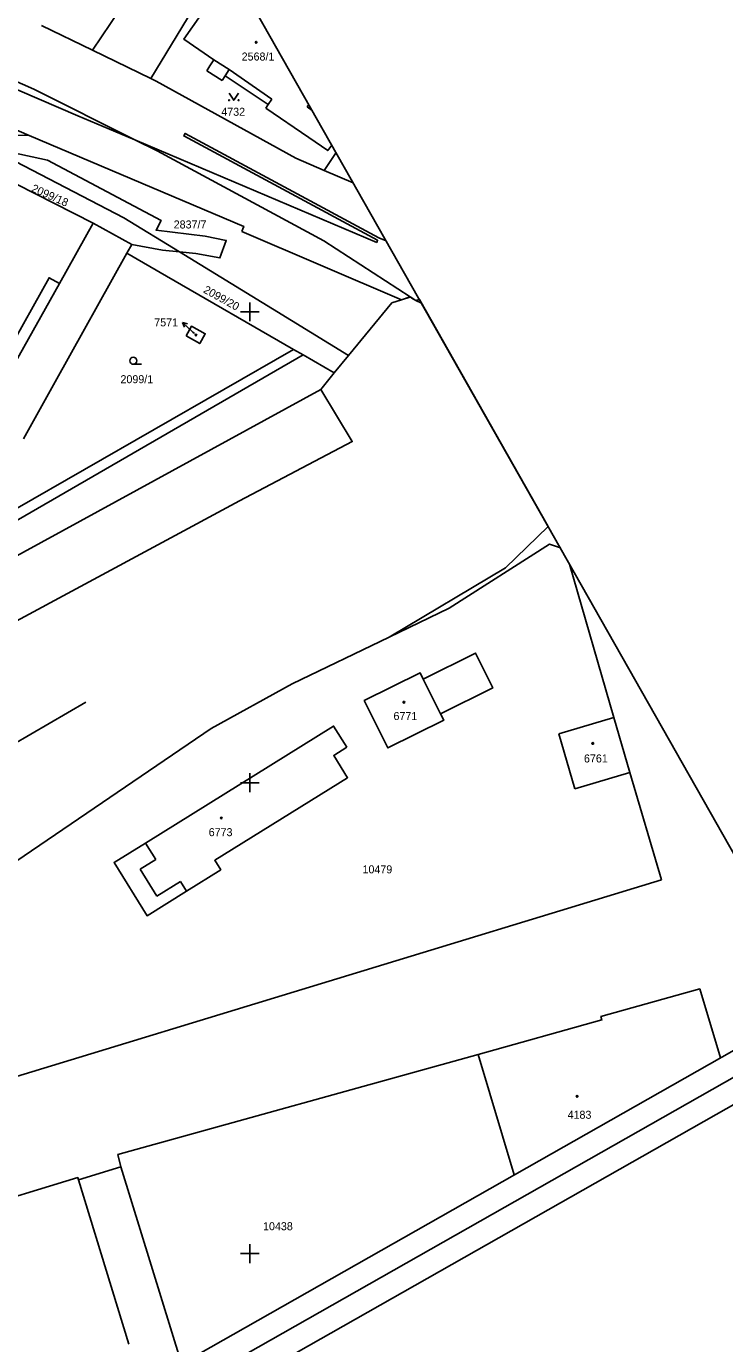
# Model space of a CAD drawing. Extents: x -566165 to -565287, y -1203064 to -1202391.
# Drawn here: x -565647.5 to -565499.2, y -1202819.1 to -1202539.4 of the extents above; entities that cross this region are included whole.
import ezdxf

# ---------------------------------------------------------------- set-up
doc = ezdxf.new("R2010")
doc.units = 0
for name, color, linetype in [('CD', 7, 'Continuous'), ('Hranice parcel', 7, 'Continuous'), ('Parcelní čísla', 7, 'Continuous'), ('Pop  PČ popisy', 7, 'Continuous'), ('Vnitřní kresba', 7, 'Continuous'), ('Vrstva 1', 7, 'Continuous'), ('Vrstva 5', 7, 'Continuous'), ('Značky budov', 7, 'Continuous'), ('Značky kultur', 7, 'Continuous'), ('ČD pro SŽDC', 7, 'Continuous')]:
    doc.layers.add(name, color=color, linetype=linetype)

msp = doc.modelspace()

# ---------------------------------------------------------------- linework, layer by layer
at = {"layer": 'CD'}
for points in [[(-565834.73, -1202732.72), (-565824.28, -1202726.13), (-565816.76, -1202721.27), (-565816.24, -1202720.98), (-565795.32, -1202709.38), (-565783.5, -1202707.11), (-565769.79, -1202704.47), (-565716.98, -1202692.29), (-565668.65, -1202665.75), (-565651.82, -1202653.08), (-565584.94, -1202616.47), (-565582.08, -1202612.99), (-565579.05, -1202609.31), (-565569.85, -1202598.11), (-565567.82, -1202597.46), (-565565.95, -1202596.85), (-565564.75, -1202597.63), (-565564, -1202597.36)], [(-565651.82, -1202653.08), (-565584.94, -1202616.47), (-565582.08, -1202612.99), (-565579.05, -1202609.31), (-565569.85, -1202598.11), (-565567.82, -1202597.46), (-565565.95, -1202596.85), (-565564.75, -1202597.63), (-565564, -1202597.36)], [(-565564, -1202597.36), (-565536.63, -1202645.61)], [(-565564, -1202597.36), (-565536.63, -1202645.61)], [(-565536.63, -1202645.61), (-565545.69, -1202654.38), (-565570.41, -1202669.07), (-565591.05, -1202679), (-565608.23, -1202688.5), (-565651.3, -1202717.76), (-565670.03, -1202715.16), (-565703.34, -1202733.61), (-565726.67, -1202746.32), (-565751.56, -1202766.01), (-565767.54, -1202780.11)], [(-565536.63, -1202645.61), (-565545.69, -1202654.38), (-565570.41, -1202669.07), (-565591.05, -1202679), (-565608.23, -1202688.5), (-565651.3, -1202717.76)]]:
    msp.add_lwpolyline(points, dxfattribs=at)
at = {"layer": 'Hranice parcel'}
for p, q in [((-565619.01, -1202523.03), (-565633.46, -1202544.45)), ((-565675.68, -1202539.58), (-565645.92, -1202552.72)), ((-565633.46, -1202544.45), (-565644.29, -1202539.18)), ((-565621.07, -1202550.47), (-565633.46, -1202544.45)), ((-565619.9, -1202551.04), (-565621.07, -1202550.47)), ((-565590.24, -1202567.4), (-565619.9, -1202551.04)), ((-565609.16, -1202548.83), (-565605.89, -1202550.88)), ((-565645.92, -1202552.72), (-565624.41, -1202563.49)), ((-565646.9, -1202562.53), (-565666.21, -1202554.22)), ((-565636.53, -1202558.35), (-565624.41, -1202563.49)), ((-565624.41, -1202563.49), (-565573.07, -1202585.25)), ((-565619.71, -1202565.84), (-565624.41, -1202563.49)), ((-565661.08, -1202567.11), (-565633.3, -1202581.16)), ((-565626.76, -1202580.01), (-565653.37, -1202566.21)), ((-565584.23, -1202569.97), (-565590.24, -1202567.4)), ((-565581.69, -1202566.18), (-565584.23, -1202569.97)), ((-565578.03, -1202572.63), (-565584.23, -1202569.97)), ((-565625.1, -1202585.67), (-565633.3, -1202581.16)), ((-565614.95, -1202587.27), (-565626.76, -1202580.01)), ((-565601.74, -1202582.95), (-565567.82, -1202597.46)), ((-565641.33, -1202614.86), (-565626.14, -1202587.55)), ((-565626.14, -1202587.55), (-565625.1, -1202585.67)), ((-565617.71, -1202592.41), (-565626.14, -1202587.55)), ((-565625.1, -1202585.67), (-565618.55, -1202586.91)), ((-565618.55, -1202586.91), (-565614.95, -1202587.27)), ((-565614.95, -1202587.27), (-565611.48, -1202587.61)), ((-565590.75, -1202607.97), (-565617.71, -1202592.41)), ((-565721.08, -1202685.53), (-565588.7, -1202609.16)), ((-565649.94, -1202642), (-565590.75, -1202607.97)), ((-565588.7, -1202609.16), (-565590.75, -1202607.97)), ((-565582.08, -1202612.99), (-565588.7, -1202609.16)), ((-565582.08, -1202612.99), (-565579.05, -1202609.31)), ((-565648.07, -1202626.98), (-565641.33, -1202614.86)), ((-565584.94, -1202616.47), (-565582.08, -1202612.99)), ((-565532.12, -1202653.56), (-565522.73, -1202686.16)), ((-565522.73, -1202686.16), (-565534.4, -1202689.63)), ((-565519.28, -1202697.85), (-565522.73, -1202686.16)), ((-565534.4, -1202689.63), (-565530.97, -1202701.28)), ((-565530.97, -1202701.28), (-565519.28, -1202697.85)), ((-565519.28, -1202697.85), (-565512.6, -1202720.6)), ((-565512.6, -1202720.6), (-565676.1, -1202770.5)), ((-565627.41, -1202781.58), (-565636.4, -1202784.32)), ((-565636.4, -1202784.32), (-565625.72, -1202819.22))]:
    msp.add_line(p, q, dxfattribs=at)
for points in [[(-565621.07, -1202550.47), (-565608.88, -1202530.33), (-565619.01, -1202523.03)], [(-565605.32, -1202529.54), (-565608.96, -1202534.8), (-565608.59, -1202535.06), (-565610, -1202537.1), (-565610.37, -1202536.85), (-565614.02, -1202542.13), (-565607.67, -1202546.46), (-565608.49, -1202547.77), (-565609.16, -1202548.83)], [(-565677.65, -1202540.7), (-565636.53, -1202558.35)], [(-565605.89, -1202550.88), (-565605.27, -1202549.9), (-565596.09, -1202555.97), (-565596.62, -1202556.75)], [(-565596.62, -1202556.75), (-565587.5, -1202563), (-565583.45, -1202565.75), (-565582.6, -1202564.58)], [(-565573.07, -1202585.25), (-565572.88, -1202584.8), (-565614.04, -1202562.63), (-565613.75, -1202562.1), (-565572.62, -1202584.26), (-565571.05, -1202584.93)], [(-565611.48, -1202587.61), (-565606.37, -1202588.55), (-565605.02, -1202584.84), (-565609.5, -1202583.94), (-565619.91, -1202582.67), (-565618.87, -1202580.59), (-565643.02, -1202567.83), (-565650.49, -1202566.2), (-565652.02, -1202564.43), (-565650.55, -1202562.52), (-565646.9, -1202562.53)], [(-565646.9, -1202562.53), (-565601.29, -1202581.88), (-565601.51, -1202582.4), (-565601.74, -1202582.95)], [(-565565.95, -1202596.85), (-565584.32, -1202584.93), (-565619.71, -1202565.84)], [(-565633.3, -1202581.16), (-565640.46, -1202593.97), (-565642.65, -1202592.75), (-565651.52, -1202608.61), (-565660.47, -1202604.69)], [(-565579.05, -1202609.31), (-565595.21, -1202599.39), (-565614.95, -1202587.27)], [(-565579.05, -1202609.31), (-565569.85, -1202598.11), (-565567.82, -1202597.46)], [(-565567.82, -1202597.46), (-565566.05, -1202596.88), (-565565.95, -1202596.85)], [(-565565.95, -1202596.85), (-565565.61, -1202597.07), (-565564.75, -1202597.63), (-565564.51, -1202597.54), (-565564, -1202597.36)], [(-565613.57, -1202605.13), (-565612.41, -1202603.05), (-565609.49, -1202604.67), (-565610.64, -1202606.75), (-565613.57, -1202605.13)], [(-565716.98, -1202692.29), (-565668.65, -1202665.75), (-565651.82, -1202653.08), (-565584.94, -1202616.47)], [(-565536.63, -1202645.61), (-565545.69, -1202654.38), (-565570.41, -1202669.07)], [(-565570.41, -1202669.07), (-565557.7, -1202662.95), (-565536.35, -1202649.35), (-565534.06, -1202650.14)], [(-565651.3, -1202717.76), (-565608.23, -1202688.5), (-565591.05, -1202679), (-565570.41, -1202669.07)], [(-565559.51, -1202685.39), (-565548.4, -1202679.87), (-565552.07, -1202672.48), (-565563.18, -1202678), (-565563.85, -1202676.66), (-565575.71, -1202682.55), (-565570.71, -1202692.62), (-565558.84, -1202686.73), (-565559.51, -1202685.39)], [(-565579.42, -1202692.47), (-565582.22, -1202687.97), (-565622.19, -1202712.8), (-565628.85, -1202716.94), (-565621.84, -1202728.24), (-565613.44, -1202723.01), (-565606.19, -1202718.49), (-565607.46, -1202716.45), (-565579.26, -1202698.93), (-565582.2, -1202694.2), (-565579.42, -1202692.47)], [(-565500.07, -1202758.42), (-565504.46, -1202743.77), (-565525.45, -1202749.61), (-565525.24, -1202750.38), (-565551.54, -1202757.69)], [(-565627.41, -1202781.58), (-565628.05, -1202778.97), (-565551.54, -1202757.69)], [(-565551.54, -1202757.69), (-565543.85, -1202783.26)], [(-565614.54, -1202823.36), (-565627.41, -1202781.58)], [(-565723.1, -1202832.75), (-565729.26, -1202812.13), (-565636.55, -1202783.84), (-565636.4, -1202784.32)]]:
    msp.add_lwpolyline(points, dxfattribs=at)
at = {"layer": 'Pop  PČ popisy'}
for p, q in [((-565612.12, -1202604.29), (-565614.32, -1202602.24)), ((-565614.32, -1202602.24), (-565613.24, -1202602.56)), ((-565614.32, -1202602.24), (-565613.92, -1202603.29)), ((-565611.78, -1202604.61), (-565612.12, -1202604.29))]:
    msp.add_line(p, q, dxfattribs=at)
at = {"layer": 'Vnitřní kresba'}
for p, q in [((-565604.4, -1202548.51), (-565607.67, -1202546.46)), ((-565604.4, -1202548.51), (-565605.27, -1202549.9)), ((-565595.31, -1202554.83), (-565604.4, -1202548.51)), ((-565595.31, -1202554.83), (-565596.09, -1202555.97)), ((-565587.85, -1202556.48), (-565587.49, -1202555.95)), ((-565587.85, -1202556.48), (-565586.76, -1202557.25)), ((-565650.02, -1202611.06), (-565640.46, -1202593.97)), ((-565563.18, -1202678), (-565559.51, -1202685.39)), ((-565622.19, -1202712.8), (-565620, -1202716.31)), ((-565620, -1202716.31), (-565623.31, -1202718.38)), ((-565623.31, -1202718.38), (-565619.74, -1202724.11)), ((-565619.74, -1202724.11), (-565614.71, -1202720.97)), ((-565614.71, -1202720.97), (-565613.44, -1202723.01))]:
    msp.add_line(p, q, dxfattribs=at)
at = {"layer": 'Vrstva 1'}
for points in [[(-566017.99, -1203063.73), (-565287.38, -1202649.25), (-565433.92, -1202390.94), (-566164.53, -1202805.42)], [(-565294.2, -1202647.37), (-566016.11, -1203056.92), (-566157.72, -1202807.3), (-565435.81, -1202397.75)], [(-566014.23, -1203050.11), (-565479.31, -1202746.65), (-565615.99, -1202505.72), (-566150.91, -1202809.18)]]:
    msp.add_lwpolyline(points, close=True, dxfattribs=at)
msp.add_lwpolyline([(-565758.48, -1202754.71), (-565721.48, -1202733.21), (-565716.28, -1202730.2), (-565687.52, -1202713.5), (-565681.68, -1202710.1), (-565634.86, -1202682.91)], dxfattribs=at)
at = {"layer": 'Vrstva 5'}
for p, q in [((-565600, -1202598), (-565600, -1202602)), ((-565602, -1202600), (-565598, -1202600)), ((-565600, -1202698), (-565600, -1202702)), ((-565602, -1202700), (-565598, -1202700)), ((-565602, -1202800), (-565598, -1202800)), ((-565600, -1202798), (-565600, -1202802))]:
    msp.add_line(p, q, dxfattribs=at)
at = {"layer": 'Značky budov'}
for centre in [(-565598.67, -1202542.77), (-565611.44, -1202604.93), (-565567.29, -1202682.91), (-565527.16, -1202691.66), (-565606.07, -1202707.5), (-565530.49, -1202766.6)]:
    msp.add_circle(centre, 0.175, dxfattribs=at)
at = {"layer": 'Značky kultur'}
msp.add_line((-565624.77, -1202611.14), (-565623.02, -1202611.14), dxfattribs=at)
msp.add_lwpolyline([(-565604.42, -1202553.56), (-565603.42, -1202555.06), (-565602.42, -1202553.56)], dxfattribs=at)
for centre, radius in [((-565604.42, -1202555.06), 0.1), ((-565602.42, -1202555.06), 0.1), ((-565624.77, -1202610.39), 0.75)]:
    msp.add_circle(centre, radius, dxfattribs=at)
at = {"layer": 'ČD pro SŽDC'}
for points in [[(-565563.53, -1202598.19), (-565564.75, -1202597.63), (-565565.61, -1202597.07), (-565565.95, -1202596.85), (-565566.05, -1202596.88), (-565567.82, -1202597.46), (-565569.85, -1202598.11), (-565579.05, -1202609.31), (-565582.08, -1202612.99), (-565584.94, -1202616.47), (-565578.25, -1202627.55), (-565602.22, -1202640.13), (-565651.5, -1202666.71), (-565690.86, -1202689.45), (-565697.77, -1202691.07), (-565753.97, -1202725.68), (-565774.54, -1202734.62), (-565818.54, -1202761.81)], [(-565563.53, -1202598.19), (-565564.75, -1202597.63), (-565565.61, -1202597.07), (-565565.95, -1202596.85), (-565566.05, -1202596.88), (-565567.82, -1202597.46), (-565569.85, -1202598.11), (-565579.05, -1202609.31), (-565582.08, -1202612.99), (-565584.94, -1202616.47), (-565578.25, -1202627.55), (-565602.22, -1202640.13), (-565651.5, -1202666.71), (-565690.86, -1202689.45), (-565697.77, -1202691.07), (-565753.97, -1202725.68), (-565774.54, -1202734.62), (-565818.54, -1202761.81)], [(-565536.63, -1202645.61), (-565563.53, -1202598.19)], [(-565536.63, -1202645.61), (-565563.53, -1202598.19)], [(-565818.54, -1202761.81), (-565796.55, -1202801.32), (-565767.54, -1202780.11), (-565751.56, -1202766.01), (-565726.67, -1202746.32), (-565725.94, -1202745.92), (-565703.34, -1202733.61), (-565670.03, -1202715.16), (-565651.3, -1202717.76), (-565608.23, -1202688.5), (-565591.05, -1202679), (-565570.41, -1202669.07), (-565545.69, -1202654.38), (-565536.63, -1202645.61)], [(-565818.54, -1202761.81), (-565796.55, -1202801.32), (-565767.54, -1202780.11), (-565751.56, -1202766.01), (-565726.67, -1202746.32), (-565725.94, -1202745.92), (-565703.34, -1202733.61), (-565670.03, -1202715.16), (-565651.3, -1202717.76), (-565608.23, -1202688.5), (-565591.05, -1202679), (-565570.41, -1202669.07), (-565545.69, -1202654.38), (-565536.63, -1202645.61)]]:
    msp.add_lwpolyline(points, dxfattribs=at)

# ---------------------------------------------------------------- texts
at = {"layer": 'Parcelní čísla'}
for s, p in [('2568/1', (-565601.75, -1202546.64)), ('4732', (-565606.08, -1202558.37)), ('2837/7', (-565616.19, -1202582.3)), ('7571', (-565620.32, -1202603.09)), ('2099/1', (-565627.49, -1202615.16)), ('6771', (-565569.5, -1202686.69)), ('6761', (-565529.04, -1202695.7)), ('6773', (-565608.75, -1202711.35)), ('10479', (-565576.08, -1202719.24)), ('4183', (-565532.52, -1202771.36)), ('10438', (-565597.21, -1202795.03))]:
    msp.add_text(s, height=1.7, dxfattribs=at).set_placement(p)
for s, rotation, p in [('2099/18', 336, (-565646.55, -1202574.38)), ('2099/20', 331, (-565610.04, -1202595.82))]:
    msp.add_text(s, height=1.7, rotation=rotation, dxfattribs=at).set_placement(p)

doc.saveas('drawing.dxf')
